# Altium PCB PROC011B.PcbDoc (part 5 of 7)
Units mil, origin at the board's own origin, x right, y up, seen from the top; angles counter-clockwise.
Board outline 3304 x 2569 mil, 6 copper layers (TOP, L2-GND1, L3-GND/SIG, L4-GND/SIG, L5-GND2, BOTTOM), stack 55.77 mil thick; 376 components, 289 nets, 1284 pads, 1755 vias.
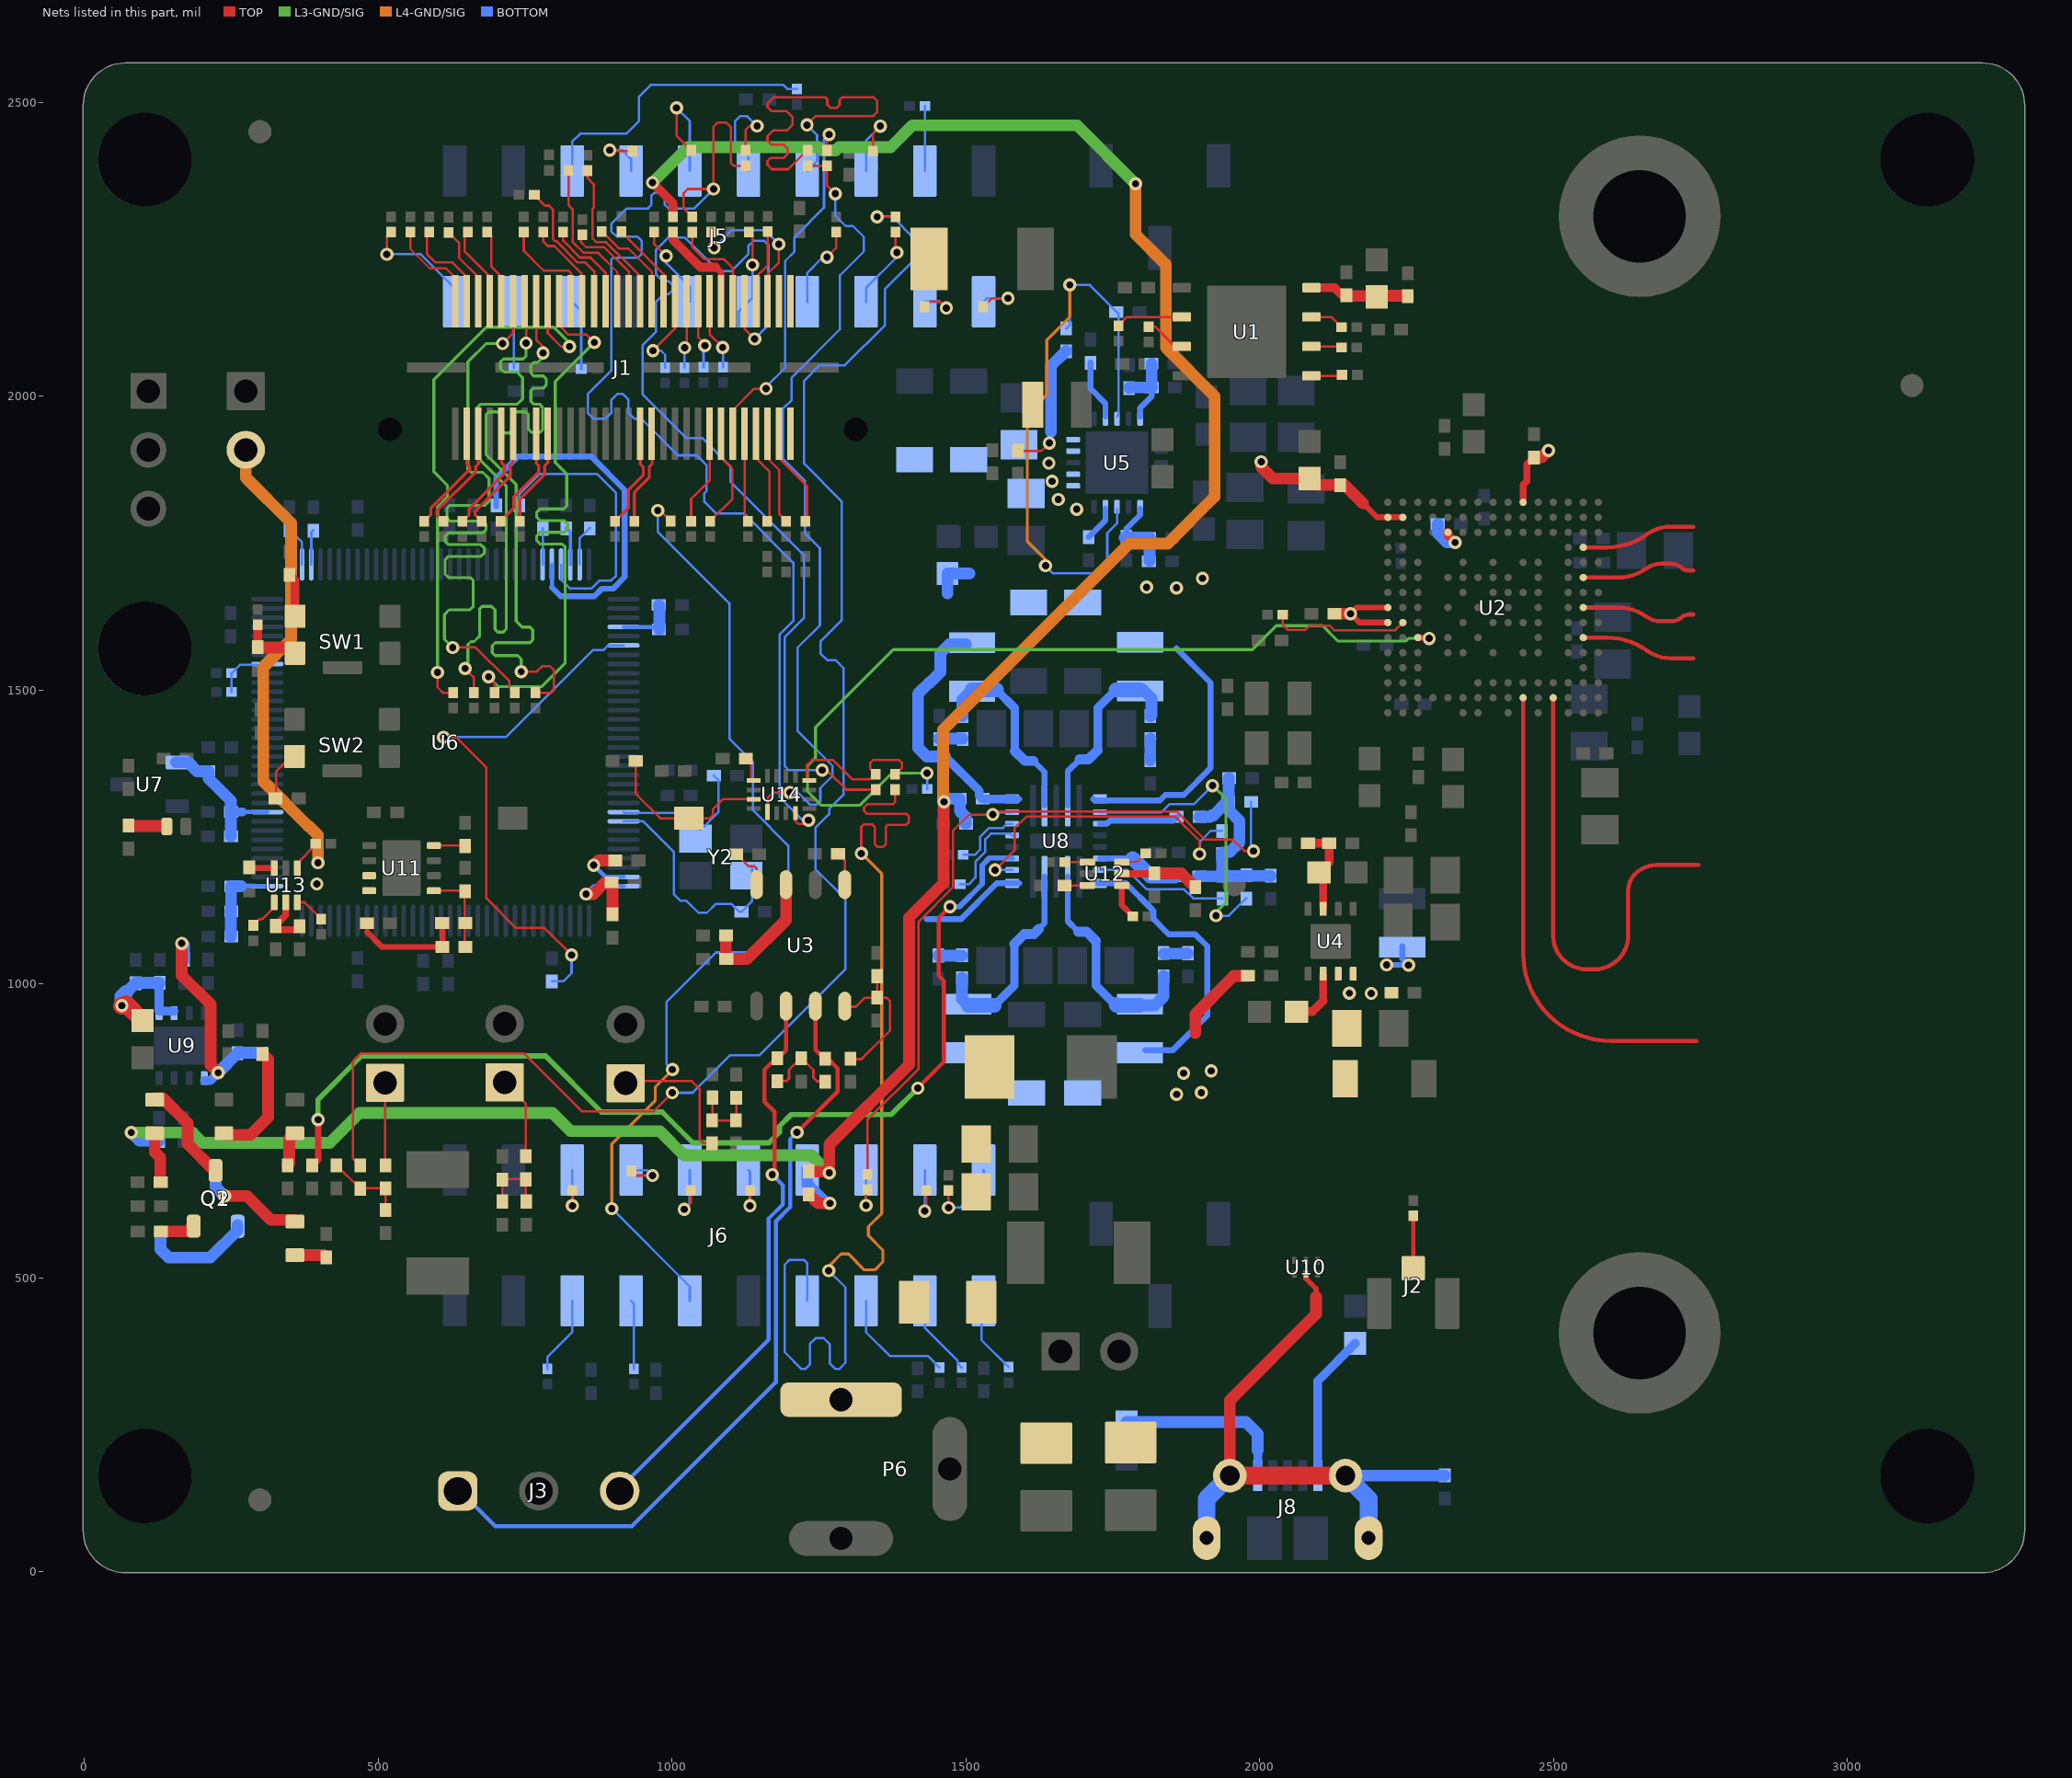
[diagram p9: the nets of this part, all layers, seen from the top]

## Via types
v1: diameter 22.4, hole 12.2, TOP to BOTTOM, tented both sides, 1046 vias
v2: diameter 13.77/15.74 (per signal layer), hole 5.9, TOP to L2-GND1, tented both sides, 699 vias
v3: diameter 19.68, hole 7.87, TOP to BOTTOM, tented both sides, 9 vias
v4: diameter 15.74, hole 5.9, TOP to L2-GND1, tented both sides, 1 vias

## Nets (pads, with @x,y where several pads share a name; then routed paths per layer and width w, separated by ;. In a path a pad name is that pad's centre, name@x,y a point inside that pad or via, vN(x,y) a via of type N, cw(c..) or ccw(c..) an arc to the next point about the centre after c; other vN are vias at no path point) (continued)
MCU_SOP2: R32.1 R101.2 | length 2731.1
  TOP w4: R101.2@469.73,690.25 469.34,690.64 456.75,703.23 456.75,868 470.75,882 748.05,882 846.65,783.4 969.15,783.4 v1(1000.55,814.8) ; v1(1348.96,2305.21) R32.1@1380.3,2305.21
  BOTTOM w4: v1(1000.55,814.8) 1035.05,814.8 1099.05,878.8 1149.05,878.8 1294.95,1024.7 1294.95,1144.76 1244.15,1195.56 1244.15,1265.26 1267.63,1288.74 1267.63,1297.52 1291.71,1321.6 1291.71,1333.55 1291.75,1333.59 1291.75,1537.5 1278.75,1550.5 1264.75,1550.5 1252.75,1562.5 1252.75,1582.6 1288.75,1618.6 1288.75,1821.1 1224.75,1885.1 1224.75,2026.11 1251.14,2052.5 1294.24,2052.5 1362.75,2121.01 1362.75,2182.5 1412.75,2232.5 1412.75,2267.5 1375.04,2305.21 v1(1348.96,2305.21)
MISO1: R6.2 R7.2 U14.1 | length 1407
  TOP w4: U14.1@1162.65,1292.68 1162.65,1316.11 1172.19,1325.65 v1(1200.62,1325.65) ; R6.2@1230.8,2392.23 R7.2@1264,2392.23 1264,2358.25 v1(1277.75,2344.5)
  BOTTOM w4: v1(1200.62,1325.65) 1214.1,1325.65 1234.35,1305.4 1246.43,1305.4 1252.45,1311.42 1252.45,1333.26 1273.22,1354.03 1273.22,1370.95 1213.58,1430.59 1213.58,1571.93 1251.65,1610 1251.65,1741.4 1226.45,1766.6 1226.45,1855.67 1188.97,1893.15 1188.97,1978.89 1203.75,1993.67 1203.75,2031.5 1285.75,2113.5 1285.75,2205.5 1326.45,2246.2 1326.45,2270.84 1307.79,2289.5 1295.75,2289.5 1277.75,2307.5 v1(1277.75,2344.5)
MOSI1: R4.2 R28.1 U14.4 | length 2092.4
  TOP w4: R28.1@1034.25,2304.89 1019.75,2319.39 1019.75,2345.5 1026.75,2352.5 v1(1070.75,2352.5) 1070.75,2458.72 1077.76,2465.73 1092.23,2465.73 1100.02,2457.94 1100.02,2396.91 1104.7,2392.23 R4.2@1125.3,2392.23 ; U14.4@1209.89,1290.71 1209.89,1276.91 1214.31,1272.49 1232.31,1272.49 1238.14,1272.49 1232.31,1278.32 v1(1232.31,1278.45)
  L3-GND/SIG w4: v1(1232.31,1278.45) 1234.92,1278.45 v1@1239,1274.37
  BOTTOM w4: v1(1070.75,2352.5) 1037.8,2319.55 994.1,2319.55 987.93,2325.72 987.93,2341.22 983.35,2345.8 969.59,2345.8 965.01,2341.22 965.01,2325.57 958.99,2319.55 923.08,2319.55 896.75,2293.22 896.75,2280.83 906.38,2271.2 941.7,2271.2 948.63,2264.27 948.63,2242.21 942.18,2235.76 900.12,2235.76 896.75,2232.39 896.75,2043.64 856.64,2003.53 856.64,1971.61 866.34,1961.91 887.35,1961.91 896.67,1971.23 896.67,1993.31 907.46,2004.1 916.27,2004.1 926.06,1994.31 926.06,1971.72 935.87,1961.91 947.65,1961.91 1010.13,1899.43 1042.02,1899.43 1059.12,1882.33 1059.12,1838.9 1055.05,1834.83 1055.05,1820.17 1074.63,1800.59 1122.39,1800.59 1206.65,1716.33 1206.65,1617.48 1183.11,1593.94 1183.11,1333.17 1182.92,1332.98 1182.92,1318.09 1226.64,1274.37 1230.72,1278.45 v1(1232.31,1278.45)
NetC1_2: C1.2 C2.2 R37.2 U1.8 | length 168.2
  TOP w15: U1.8@2090.08,2184.68 2127.56,2184.68 2140.14,2172.1 C2.2@2147.65,2172.1
  TOP w20: C2.2@2147.65,2172.1 2147.84,2171.91 2149.15,2170.6 2199.35,2170.6 2199.75,2171 R37.2@2252.25,2171
NetC16_2: C16.2 R78.1 U3.3 | length 230.9
  TOP w20: C16.2@1091.65,1082.5 1091.65,1042.5 R78.1@1092.43,1042.5 1127.75,1042.5 1194.06,1108.81 U3.3@1194.06,1168.83 U3.3@1194.06,1169.81
NetC18_1: C18.1 R81.2 R82.1 U4.3 | length 156
  TOP w13: C18.1@2101.12,1189.37 2108.13,1182.36 U4.3@2108.13,1130.54
  TOP w15: R81.2@2081.54,1239.67 R81.2@2082.33,1239.67 2118.38,1239.67 2118.38,1206.62 C18.1@2101.12,1189.37
NetC22_2: C22.2 U4.6 | length 96.1
  TOP w13: 2108.13,971.38 U4.6@2108.13,1014.4
  TOP w15: C22.2@2062.72,952.77 2062.95,953 2089.75,953 2108.13,971.38
NetC24_2: C24.2 R85.1 R87.2 | length 129.4
  TOP w4: R87.2@1179.45,835 1195.35,835 1199.25,838.9 1199.25,853.9 1218.25,872.9 1219.85,872.9 1221.45,872.9 1240.75,853.6 1240.75,840.5 1246.85,834.4 R85.1@1260.75,834.4
NetC26_1: C26.1 C27.1 D3.1 F1.1 FB1.1 FB2.1
NetC28_1: C28.1 R121.2 R122.1 U5.10 | length 138.7
  BOTTOM w10: U5.10@1796.74,1965.56 1796.74,1980.04 1816.35,1999.65 1816.35,2014.14 R122.1@1816.35,2014.92
  BOTTOM w12: R122.1@1816.35,2014.14 R122.1@1817.13,2014.92
  BOTTOM w20: R121.2@1778.02,2014.49 1778.45,2014.92 R122.1@1816.35,2014.92 1817.13,2014.92 1816.45,2015.6 C28.1@1816.45,2055.5
NetC29_2: C29.2 U5.7 | length 102.2
  BOTTOM w10: C29.2@1712.22,2057.25 C29.2@1712.22,2056.86 1712.22,2013.03 1737.68,1987.57 U5.7@1737.68,1965.56
NetC44_2: C44.2 U5.19 | length 59.9
  BOTTOM w10: C44.2@1708.92,1760.05 1709.11,1760.24 1737.68,1788.81 U5.19@1737.68,1808.08
NetC46_1: C46.1 R131.1 R132.2 U5.16 | length 147.1
  BOTTOM w10: R132.2@1770.69,1759.28 1773.22,1759.75 1771.22,1759.75 R132.2@1773.22,1761.75 ; R132.2@1773.22,1760.54 R132.2@1773.22,1761.75 ; U5.16@1796.74,1808.08 1796.74,1798.16 1773.22,1774.64 R132.2@1773.22,1761.75 ; C46.1@1811.95,1719.02 C46.1@1812.59,1719.66
  BOTTOM w20: R132.2@1770.69,1759.28 R131.1@1811.81,1759.28 1812.59,1759.28 C46.1@1812.59,1719.66
NetC49_2: C49.2 R134.1 U6.68 | length 104.2
  BOTTOM w7: U6.68@917.69,1607.39 974.21,1607.39 978.11,1603.49 R134.1@978.5,1603.1
  BOTTOM w20: C49.2@977.8,1644.4 978.5,1643.7 R134.1@978.5,1603.1
NetC63_2: C63.2 U6.88 Y2.1 | length 251.3
  BOTTOM w4: U6.88@917.69,1292.43 919.12,1291 1018.74,1291 1046.96,1262.78 1049.4,1262.78 1079.3,1292.68 1079.3,1346.36 C63.2@1071.31,1354.35
NetC66_2: C66.2 C67.2 R140.1 U6.9 U7.1 | length 250.2
  BOTTOM w7: 269.42,1292.43 U6.9@311.39,1292.43
  BOTTOM w15: C66.2@249.24,1292.6 C66.2@249.63,1292.6 269.25,1292.6 269.42,1292.43
  BOTTOM w20: U7.1@156.11,1376.99 U7.1@158.07,1376.99 176.75,1376.99 191.72,1362.02 R140.1@210.71,1362.02 211.5,1362.02 211.5,1349.25 249.24,1311.51 249.24,1292.6 249.24,1251.36 C67.2@249.3,1251.3
NetC70_2: C70.2 U6.89 Y2.3 | length 403.5
  BOTTOM w4: U6.89@917.69,1276.68 951.07,1276.68 1003.45,1224.3 1003.45,1152.38 1014.36,1141.47 1024.62,1141.47 1044.92,1121.18 1059.56,1121.18 1074.79,1136.41 1100.86,1136.41 1114.57,1122.7 C70.2@1118.25,1122.7 1136.02,1140.47 1136.02,1184.08 Y2.3@1136.02,1199.78
NetC71_2: C71.2 R154.1 U6.96 | length 174.6
  TOP w20: v1(853.75,1153) 866.39,1153 886.39,1173 C71.2@897.06,1173 C71.2@897.45,1173 ; R154.1@898.75,1118.18 C71.2@898.75,1171.31
  BOTTOM w7: v1(853.75,1153) 867.2,1166.45 U6.96@917.69,1166.45
NetC78_1: C78.1 R156.1 R157.2 U9.5 | length 394
  TOP w20: v1(165.75,1069) 165.75,1014.4 214.75,965.4 214.75,862 v1(227.75,849)
  BOTTOM w15: U9.5@203.97,835.82 214.57,835.82 v1(227.75,849)
  BOTTOM w20: v1(165.75,1069) 166.75,1069 169.85,1065.9 C78.1@169.85,1041.33 C78.1@169.85,1040.95 ; v1(227.75,849) R156.1@260.78,882 ; R156.1@260.78,882 260.78,882.79 301.61,882.79 R157.2@301.95,882.45
NetC79_2: C79.2 C80.2 R176.1 U9.1 U9.2 | length 211.7
  TOP w30: v1(63.75,963) 67.75,963 70.5,965.75 70.75,966 98.75,938 R176.1@98.75,937.5
  BOTTOM w15: C79.2@128.37,1002.05 128.18,1001.86 128.02,1001.7 127.19,1000.87 127.19,953.94 U9.2@152.78,953.94
  BOTTOM w20: 70.75,985.1 87.16,1001.51 87.35,1001.7 C79.2@128.02,1001.7
  BOTTOM w25: v1(63.75,963) 63.75,978.1 70.75,985.1
NetC85_2: C85.2 C88.1 P7.2 R61.2 U11.3 U11.4 | length 972.9
  TOP w10: 481.35,1088.1 506.55,1062.9 C88.1@609.07,1062.9 609.45,1062.9 609.65,1063.1 R61.2@609.65,1103.6
  L4-GND/SIG w20: P7.2@274.69,1908.65 274.69,1861.56 351.75,1784.5 351.75,1586.5 304.35,1539.1 304.35,1345.1 380.55,1268.9 381.85,1268.9 397.65,1253.1 v1(397.65,1206)
  other v1: 395.65,1170
NetC88_2: C88.2 R61.1 R193.2 U11.5 | length 145
  TOP w4: U11.5@598.71,1158.61 647.65,1158.61 647.45,1158.41 647.45,1157.82 647.45,1103.6 647.45,1063.5 C88.2@648.05,1062.9
NetC91_2: C91.2 R196.1 U12.5 | length 135.4
  TOP w12: U12.5@1765.38,1187.4 1820.65,1187.4 C91.2@1821.15,1187.9
  TOP w20: C91.2@1821.15,1187.9 1866.65,1187.9 1890.26,1164.29 R196.1@1890.65,1163.9
NetC92_2: C92.2 R200.1 U13.5 | length 94.9
  TOP w12: U13.5@342.75,1138.77 342.75,1117.3 324.3,1098.85 331.15,1092 360.35,1092 C92.2@366.35,1098
NetC93_2: C93.2 R202.1 | length 40.2
  BOTTOM w20: C93.2@1454.45,1417.1 1454.85,1417.5 R202.1@1494.45,1417.5
NetC94_2: C94.2 R203.1 | length 37.4
  BOTTOM w20: C94.2@1814.05,1380.1 C94.2@1814.05,1380.49 1814.05,1416.61 1814.05,1417.2 R203.1@1814.25,1417.4
NetC95_2: C95.2 R204.1 | length 40.4
  BOTTOM w20: C95.2@1453.15,1048 1453.34,1048.19 R204.1@1493.45,1048.2
NetC96_2: C96.2 R205.1 | length 41.3
  BOTTOM w20: R205.1@1836.65,1051.7 1877.65,1051.7 C96.2@1877.85,1051.9
NetD2_1: D2.1 R80.2 | length 67.8
  TOP w10: D2.1@139.05,1268.56 139.64,1267.97 D2.1@140.24,1267.97 D2.1@143.09,1267.97
  TOP w20: R80.2@75.5,1268.56 D2.1@139.05,1268.56
NetDS1_1: DS1.1 R90.1 | length 200
  TOP w20: DS1.1@237.46,743.13 282.88,743.13 312.75,773 312.75,871.85 303.6,881 R90.1@303.21,881.39
NetDS2_1: DS2.1 R100.1 | length 59.8
  TOP w20: R100.1@345.66,691.25 348.75,694.33 348.75,736.23 DS2.1@358.35,745.83
NetDS3_1: DS3.1 R103.1 | length 84.2
  TOP w20: DS3.1@119.78,742.81 119.78,713.97 129.22,704.53 R103.1@129.22,662.57
NetDS3_2: DS3.2 Q1.3 | length 175.9
  TOP w20: DS3.2@119.78,805.81 132.94,805.81 175.65,763.1 175.65,728.21 222.35,681.51 Q1.3@223.33,680.53
NetDS4_1: DS4.1 R117.1 | length 54.4
  TOP w20: DS4.1@358.35,538.42 407.91,538.42 R117.1@411.36,534.96
NetDS4_2: DS4.2 Q2.3 | length 183.7
  TOP w20: v1(238.75,639) 277.06,639 317.6,598.46 DS4.2@358.35,598.46
  BOTTOM w20: Q2.3@223.37,679.95 223.37,654.38 v1(238.75,639)
NetF1_2: F1.2 P6.1
NetJ1_1: J1.1 J1.2 J1.3 R34.1
NetJ1_4: J1.4 R67.1 | length 169.2
  TOP w4: J1.4@1182.55,1935.77 1182.55,1893.9 1229.75,1846.7 1229.75,1789.96 R67.1@1227,1787.21
NetJ1_5: J1.5 R29.2 | length 265.8
  TOP w4: R29.2@1066.58,2279.23 1066.58,2257.67 v1(1071.75,2252.5) ; J1.5@1162.86,2161.75 1162.86,2208.61 1181.75,2227.5 v1(1181.75,2258.5)
  BOTTOM w4: v1(1071.75,2252.5) 1101.75,2282.5 1157.75,2282.5 v1(1181.75,2258.5)
NetJ1_6: J1.6 R66.1 | length 161.7
  TOP w4: J1.6@1162.86,1935.77 1162.86,1893.9 1182.75,1874.01 1182.75,1798.96 R66.1@1194.5,1787.21
NetJ1_7: J1.7 R17.2 | length 126.7
  TOP w4: J1.7@1143.18,2161.75 1143.18,2202.93 1163,2222.75 R17.2@1163,2280.23
NetJ1_8: J1.8 R65.1 | length 159.6
  TOP w4: J1.8@1143.18,1935.77 1143.18,1894.58 1165.95,1871.81 1165.95,1791.16 R65.1@1162,1787.21
NetJ1_9: J1.9 R75.2 | length 1734.2
  TOP w4: J1.9@1123.49,2161.75 1123.49,2161.56 1123.49,2114.76 v1(1140.75,2097.5) ; v1(1255.52,1363.62) 1263.64,1363.62 1296.76,1330.51 R75.2@1346.75,1330.51
  BOTTOM w4: v1(1140.75,2097.5) 1164.05,2120.8 1164.05,2257.15 1156.46,2264.74 1139.39,2264.74 1129.85,2255.2 1129.85,2241.53 1100.94,2212.62 1079.22,2212.62 1022.14,2269.7 993.68,2269.7 972.45,2248.47 972.45,2207.63 984.38,2195.7 994.44,2195.7 1001.13,2189.01 1001.13,2180.38 994.43,2173.68 985.82,2173.68 972.45,2160.31 972.45,2109.37 949.76,2086.68 949.76,2003.46 1024.13,1929.09 1051.28,1929.09 1099.45,1880.92 1099.45,1854.8 1224.65,1729.6 1224.65,1622.75 1192.11,1590.21 1192.11,1370.14 1198.63,1363.62 v1(1255.52,1363.62)
NetJ1_10: J1.10 R64.1 | length 151
  TOP w4: J1.10@1123.49,1935.77 1123.49,1793.08 R64.1@1129.36,1787.21
NetJ1_11: J1.11 R28.2 | length 165.5
  TOP w4: R28.2@1034.25,2278.91 1034.25,2254 1054.75,2233.5 1088.16,2233.5 1103.81,2217.85 J1.11@1103.81,2161.75
NetJ1_12: J1.12 R7.1 | length 617.8
  TOP w4: J1.12@1103.4,1935.96 1103.4,1976.36 1139.88,2012.84 v1(1160.01,2012.84) ; J1.12@1103.81,1935.77 J1.12@1103.81,1935.96 ; R7.1@1264,2418.21 1264,2442.11 v1(1267.28,2445.39)
  BOTTOM w4: v1(1160.01,2012.84) 1160.01,2015.76 1192.62,2048.37 1192.62,2230.05 1208.45,2245.87 1208.45,2270.6 1258.75,2320.9 1258.75,2436.86 v1(1267.28,2445.39)
NetJ1_13: J1.13 R27.2 | length 167
  TOP w10: 1074.75,2219.5 1084.12,2210.13 J1.13@1084.12,2161.75
  TOP w15: R27.2@1001.55,2279.01 1001.55,2266.2 1048.25,2219.5 1074.75,2219.5
NetJ1_14: J1.14 R63.1 | length 172
  TOP w4: R63.1@1064.86,1787.21 1102.75,1825.1 1102.75,1875.89 1084.12,1894.52 J1.14@1084.12,1935.77
NetJ1_15: J1.15 R54.2 | length 121.7
  TOP w4: J1.15@1064.03,2161.56 1064.03,2105.22 v1(1086.25,2083) ; J1.15@1064.44,2161.56 J1.15@1064.44,2161.75
  BOTTOM w4: v1(1086.25,2083) 1086.75,2082.5 R54.2@1086.75,2049.49
NetJ1_16: J1.16 R62.1 | length 161.7
  TOP w4: R62.1@1032.6,1787.21 1032.6,1825.35 1064.44,1857.19 J1.16@1064.44,1935.77
NetJ1_17: J1.17 R55.2 | length 117.9
  TOP w4: J1.17@1044.75,2161.75 1044.75,2161.56 1044.75,2100.5 1055.87,2089.38 v1(1055.87,2086.09)
  BOTTOM w4: R55.2@1053.75,2049.29 1053.75,2075.5 1055.87,2077.62 v1(1055.87,2086.09)
NetJ1_19: J1.19 R56.2 | length 114.5
  TOP w4: v1(1021.75,2082.5) 1025.07,2085.82 1025.07,2161.56 J1.19@1025.07,2161.75
  BOTTOM w4: R56.2@1021.25,2048.79 1021.25,2082 v1(1021.75,2082.5)
NetJ1_21: J1.21 R57.2 | length 145
  TOP w4: v1(967.75,2077.5) 1005.38,2115.13 1005.38,2161.56 J1.21@1005.38,2161.75
  BOTTOM w4: v1(967.75,2077.5) 981.25,2077.5 988.35,2070.4 R57.2@988.35,2048.79
NetJ1_23: J1.23 R179.2 | length 148.1
  TOP w4: R179.2@913.75,2280.01 985.7,2208.06 J1.23@985.7,2161.75
NetJ1_25: J1.25 R180.2 | length 163.6
  TOP w4: R180.2@880.45,2280.21 881.04,2280.21 909.75,2251.5 925.75,2251.5 966.01,2211.24 J1.25@966.01,2161.75
NetJ1_26: J1.26 R59.1 | length 161.1
  TOP w5.2: R59.1@935.8,1787.21 935.8,1836.05 961.27,1861.52 961.27,1879.81 966.01,1884.55 J1.26@966.01,1935.77
NetJ1_27: J1.27 R181.2 | length 270.8
  TOP w4: R181.2@856.25,2383.81 856.25,2371 866.75,2360.5 866.75,2320.5 864.75,2318.5 864.75,2268.5 871.25,2262 887.85,2262 946.33,2203.52 J1.27@946.33,2161.75
NetJ1_28: J1.28 R58.1 | length 170.3
  TOP w5.2: R58.1@903.3,1787.21 925.6,1809.51 925.6,1840.28 951.07,1865.75 951.07,1879.81 946.33,1884.55 J1.28@946.33,1935.77
NetJ1_29: J1.29 R182.2 | length 166.1
  TOP w4: R182.2@847.75,2274.51 844.75,2271.51 844.75,2262.51 853.76,2253.5 884.75,2253.5 926.64,2211.61 J1.29@926.64,2161.75
NetJ1_31: J1.31 R183.2 | length 271.6
  TOP w4: R183.2@823.75,2384.21 823.75,2325.1 830.75,2318.1 830.75,2262.5 849.05,2244.2 874.05,2244.2 906.96,2211.29 J1.31@906.96,2161.75
NetJ1_33: J1.33 R184.2 | length 158.3
  TOP w4: R184.2@814.75,2279.51 814.75,2264.51 843.36,2235.9 861.35,2235.9 887.27,2209.98 J1.33@887.27,2161.75
NetJ1_35: J1.35 R185.2 | length 235.8
  TOP w4: R185.2@765.74,2342.5 783.94,2324.3 790.95,2324.3 797.35,2317.9 797.35,2267.9 801.75,2263.5 803.75,2263.5 839.65,2227.6 852.55,2227.6 867.59,2212.56 J1.35@867.59,2161.75
NetJ1_37: J1.37 R186.2 | length 151.9
  TOP w4: R186.2@781.05,2279.51 781.05,2263.2 788.75,2255.5 799.75,2255.5 845.75,2209.5 845.75,2163.9 847.79,2161.86 J1.37@847.9,2161.75
NetJ1_39: J1.39 R187.2 | length 176
  TOP w4: R187.2@747.75,2279.51 747.75,2247.5 781.75,2213.5 824.22,2213.5 828.22,2209.5 J1.39@828.22,2161.75
NetJ1_41: J1.41 R188.2 | length 1058.5
  TOP w4: v1(687.75,1522.6) 697.75,1512.6 R188.2@697.75,1495.59 ; J1.41@808.53,2161.75 808.53,2161.56 808.53,2119.92 823.95,2104.5 854.75,2104.5 v1(867.75,2091.5)
  L3-GND/SIG w5: v1(687.75,1522.6) 704.77,1505.58 777.83,1505.58 818.25,1546 818.25,1743.34 813.25,1748.34 775.61,1748.34 769.75,1754.2 769.75,1762.48 775.61,1768.34 816.89,1768.34 822.75,1774.2 822.75,1782.48 816.89,1788.34 775.61,1788.34 769.75,1794.2 769.75,1802.48 775.61,1808.34 815.85,1808.34 820.85,1813.34 820.85,1867.9 801.35,1887.4 801.35,2025.1 v1(867.75,2091.5)
NetJ1_43: J1.43 R189.2 | length 956.7
  TOP w4: v1(601.05,1530.2) 601.05,1504.6 610.06,1495.59 R189.2@627.75,1495.59 ; J1.43@788.44,2161.56 788.44,2107.29 811.23,2084.5 v1(825.75,2084.5) ; J1.43@788.85,2161.56 J1.43@788.85,2161.75
  L3-GND/SIG w5: v1(601.05,1530.2) 601.05,1811.8 617.75,1828.5 617.75,1848.5 594.75,1871.5 594.75,2028 684.25,2117.5 798.75,2117.5 825.75,2090.5 v1(825.75,2084.5)
NetJ1_44: J1.44 R53.1 | length 168.4
  TOP w5.2: R53.1@741,1787.21 741,1824.74 783.25,1866.99 783.25,1881.49 788.85,1887.09 J1.44@788.85,1935.77
NetJ1_45: J1.45 R190.2 | length 1191.9
  TOP w4: v1(743.45,1531.4) 769.65,1531.4 778.75,1540.5 792.75,1540.5 798.75,1534.5 798.75,1499.59 794.75,1495.59 R190.2@767.75,1495.59 ; J1.45@769.16,2161.75 769.16,2161.56 769.16,2096.09 780.75,2084.5 v1(780.75,2073.5) v1@780.75,2072.5
  L3-GND/SIG w5: v1(743.45,1531.4) 743.45,1552.7 737.55,1558.6 699.29,1558.6 694.29,1563.6 694.29,1575.5 699.29,1580.5 758.15,1580.5 763.15,1585.5 763.15,1602.2 758.15,1607.2 744.75,1607.2 734.75,1617.2 734.75,1849.5 683.75,1900.5 683.75,1968.5 688.75,1973.5 703.18,1973.5 709.04,1967.64 709.04,1943.36 714.9,1937.5 723.18,1937.5 729.04,1943.36 729.04,1967.64 734.9,1973.5 750.75,1973.5 755.75,1968.5 755.75,1943.5 760.75,1938.5 775.75,1938.5 779.75,1942.5 779.75,1981.5 774.75,1986.5 764.75,1986.5 759.75,1991.5 759.75,2009.5 763.75,2013.5 780.95,2013.5 785.95,2018.5 785.95,2029.5 780.95,2034.5 764.87,2034.5 759.87,2039.5 759.87,2052.5 764.87,2057.5 771.75,2057.5 780.75,2066.5 v1@780.75,2072.5
NetJ1_46: J1.46 R52.1 | length 176.9
  TOP w5.2: R52.1@708.5,1787.21 730.8,1809.51 730.8,1828.97 773.05,1871.22 773.05,1881.7 769.16,1885.59 J1.46@769.16,1935.77
NetJ1_47: J1.47 R191.2 | length 963.5
  TOP w4: v1(647.85,1536.7) 662.75,1521.8 R191.2@662.75,1495.59 ; J1.47@749.48,2161.75 751.75,2159.48 v1(751.75,2090.5)
  L3-GND/SIG w5: v1(647.85,1536.7) 652.75,1541.6 652.75,1577.5 657.75,1582.5 663.16,1582.5 672.75,1592.09 672.75,1638.5 676.75,1642.5 692.75,1642.5 698.75,1636.5 698.75,1603.5 703.75,1598.5 712.75,1598.5 717.85,1603.6 717.85,1847.4 667.75,1897.5 667.75,1979.51 674.74,1986.5 736.75,1986.5 745.75,1995.5 745.75,2031.5 736.25,2041 714.25,2041 708.29,2046.96 708.29,2058.5 713.29,2063.5 746.75,2063.5 751.75,2068.5 v1(751.75,2090.5)
NetJ1_49: J1.49 R192.2 | length 1204.6
  TOP w4: v1(626.75,1572.4) 665.85,1572.4 723.15,1515.1 723.15,1505.19 R192.2@732.75,1495.59 ; v1(711.75,2089.5) 729.79,2107.54 729.79,2161.56 J1.49@729.79,2161.75
  L3-GND/SIG w5: v1(626.75,1572.4) 612.75,1586.4 612.75,1628.5 620.75,1636.5 655.75,1636.5 661.75,1642.5 661.75,1686.5 656.75,1691.5 619.75,1691.5 613.75,1697.5 613.75,1721.57 619.61,1727.43 674.89,1727.43 680.75,1733.29 680.75,1741.57 674.89,1747.43 619.61,1747.43 613.75,1753.29 613.75,1761.57 619.61,1767.43 677.89,1767.43 683.75,1773.29 683.75,1781.57 677.89,1787.43 621.95,1787.43 616.95,1792.43 616.95,1809.3 621.95,1814.3 681.55,1814.3 688.75,1821.5 688.75,1859.8 678.05,1870.5 657.75,1870.5 652.75,1875.5 652.75,2058.35 683.9,2089.5 v1(711.75,2089.5)
NetJ1_50: J1.50 R51.1 | length 180.1
  TOP w5.2: R51.1@676,1787.21 664.85,1798.36 664.85,1804.11 724.75,1864.01 724.75,1883.01 729.79,1888.05 J1.50@729.79,1935.77
NetJ1_51: J1.51 R23.2 | length 127.7
  TOP w4: R23.2@685.36,2279.23 692.75,2271.84 692.75,2220.5 710.11,2203.14 J1.51@710.11,2161.75
NetJ1_52: J1.52 R50.1 | length 179.8
  TOP w5.2: R50.1@643.5,1787.21 654.65,1798.36 654.65,1808.34 714.55,1868.24 714.55,1882.21 710.11,1886.65 J1.52@710.11,1935.77
NetJ1_53: J1.53 R22.2 | length 137.5
  TOP w4: R22.2@652.86,2279.23 647.45,2273.82 647.45,2245.81 690.42,2202.84 J1.53@690.42,2161.75
NetJ1_55: J1.55 R33.2 | length 138
  TOP w4: R33.2@620.14,2278.79 637.75,2261.18 637.75,2235.5 670.74,2202.51 J1.55@670.74,2161.75
NetJ1_56: J1.56 R49.1 | length 182.6
  TOP w5.2: R49.1@611,1787.21 599.78,1798.43 599.78,1805.03 665.95,1871.2 665.95,1880.38 670.74,1885.17 J1.56@670.74,1935.77
NetJ1_57: J1.57 R21.2 | length 164.6
  TOP w4: R21.2@587.1,2279.23 582.75,2274.88 582.75,2242.51 597.76,2227.5 626.75,2227.5 651.05,2203.2 J1.57@651.05,2161.75
NetJ1_58: J1.58 R48.1 | length 182.6
  TOP w5.2: R48.1@578.36,1787.21 589.58,1798.43 589.58,1809.26 655.75,1875.43 655.75,1879.85 651.05,1884.55 J1.58@651.05,1935.77
NetJ1_59: J1.59 R20.2 | length 165.6
  TOP w4: R20.2@554.86,2279.23 554.86,2250.39 587.75,2217.5 615.76,2217.5 631.37,2201.89 J1.59@631.37,2161.75
NetJ2_1: J2.1 R111.2 | length 89.5
  TOP w7.08: J2.1@2261.46,516.26 2261.61,516.41 R111.2@2261.61,605.68
NetJ3_1: J3.1 R85.2 U3.7 | length 1370.5
  TOP w7: v1(1212.75,747.5) 1281.85,816.6 1281.85,856.3 1265.95,872.2 1260.75,872.2 1259.75,872.2 1244.06,887.89 U3.7@1244.06,961.15
  BOTTOM w7: J3.1@635.55,141.16 637.52,139.19 699.18,77.53 931.78,77.53 1176.75,322.5 1176.75,596.1 1200.95,620.3 1200.95,735.7 v1(1212.75,747.5)
NetJ3_3: J3.3 R87.1 U3.6 | length 968.7
  TOP w7: v1(1170.75,675.5) 1174.75,679.5 1174.75,782.3 1157.25,799.8 1157.25,854 1176.05,872.8 1179.45,872.8 1179.84,873.19 1194.06,887.41 U3.6@1194.06,961.15
  BOTTOM w7: J3.3@911.14,141.16 1164.75,394.77 1164.75,601.1 1188.95,625.3 1188.95,657.3 v1(1170.75,675.5)
NetJ5_1: J5.1 R19.2 | length 203
  TOP w4: v1(514.75,2241.5) 514.75,2271.98 R19.2@522,2279.23
  BOTTOM w4: v1(514.75,2241.5) 572.25,2241.5 630.25,2183.5 J5.1@630.25,2160.78
NetJ5_3: J5.3 R24.2 | length 112.9
  BOTTOM w4: J5.3@730.25,2160.78 730.86,2160.17 R24.2@730.86,2048.1
NetJ5_5: J5.5 R25.2 | length 120.8
  BOTTOM w4: J5.5@830.25,2160.78 845.56,2145.47 R25.2@845.56,2046.3
NetJ5_6: J5.6 R1.1 | length 499.1
  BOTTOM w4: J5.6@830.25,2383.22 830.25,2432.9 843.85,2446.5 922.35,2446.5 943.45,2467.6 943.45,2509.1 963.75,2529.4 1189.81,2529.4 1196.72,2522.49 R1.1@1212.55,2522.49
NetJ5_8: J5.8 R9.1 | length 102
  TOP w4: v1(893.95,2418.7) 895.44,2417.21 R9.1@932.5,2417.21
  BOTTOM w4: v1(893.95,2418.7) 914.95,2418.7 930.25,2403.4 J5.8@930.25,2383.22
NetJ5_9: J5.9 R26.2 | length 143.5
  TOP w4: R26.2@969.45,2279.11 969.45,2259.2 v1(990.15,2238.5)
  BOTTOM w4: v1(990.15,2238.5) 990.15,2226.45 1030.25,2186.35 J5.9@1030.25,2160.78
NetJ5_10: J5.10 R2.1 | length 199.3
  TOP w4: v1(1007.75,2490.5) 1007.75,2443.26 R2.1@1032.8,2418.21
  BOTTOM w4: v1(1007.75,2490.5) 1030.25,2468 J5.10@1030.25,2383.22
NetJ5_11: J5.11 R18.2 | length 172.7
  TOP w4: R18.2@1130.96,2279.58 1131.17,2279.58 1136.85,2273.9 v1(1136.85,2223.5)
  BOTTOM w4: J5.11@1113.17,2119.29 1113.17,2143.7 J5.11@1130.25,2160.78 1136.85,2167.38 v1(1136.85,2223.5)
NetJ5_12: J5.12 R4.1 | length 199.5
  TOP w4: R4.1@1125.3,2418.21 1125.3,2453.37 1131.58,2459.65 v1(1144.9,2459.65)
  BOTTOM w4: J5.12@1130.25,2383.22 1130.25,2410.9 1107.4,2433.75 1107.4,2468.08 1115.64,2476.32 1128.23,2476.32 v1(1144.9,2459.65)
NetJ5_13: J5.13 R31.2 | length 142.9
  TOP w4: v1(1263.75,2236.5) 1279.5,2252.25 R31.2@1279.5,2279.23
  BOTTOM w4: J5.13@1230.25,2160.78 1230.25,2209.97 1256.78,2236.5 v1(1263.75,2236.5)
NetJ5_14: J5.14 R6.1 | length 765.3
  TOP w4: v1(1229.75,2461.5) 1244.95,2476.7 1342.73,2476.7 1349.14,2483.11 1349.14,2502.84 1343.4,2508.58 1289.89,2508.58 1285.34,2504.03 1285.34,2495.57 1280.64,2490.87 1269.58,2490.87 1264.22,2496.23 1264.22,2505.35 1260.99,2508.58 1173.01,2508.58 1162.45,2498.02 1162.45,2491.95 1169.58,2484.82 1195.05,2484.82 1205.35,2474.52 1205.35,2462.24 1195.06,2451.95 1172.03,2451.95 1162.45,2442.37 1162.45,2434.73 1169.38,2427.8 1190.59,2427.8 1196.18,2422.21 1196.18,2411.25 1190.37,2405.44 1168.04,2405.44 1162.45,2399.85 1162.45,2393.77 1170.05,2386.17 1197.52,2386.17 1229.56,2418.21 R6.1@1230.8,2418.21
  BOTTOM w4: v1(1229.75,2461.5) 1247.02,2444.23 1247.02,2399.99 J5.14@1230.25,2383.22
NetJ5_15: J5.15 R32.2 | length 141.2
  TOP w4: R32.2@1380.3,2279.23 1380.75,2278.78 1380.75,2246.5 v1(1382.75,2244.5)
  BOTTOM w4: J5.15@1330.25,2160.78 1330.25,2184 1382.75,2236.5 v1(1382.75,2244.5)
NetJ5_16: J5.16 R10.1 | length 134
  TOP w4: R10.1@1342,2417.21 1342,2446.75 v1(1354.75,2459.5)
  BOTTOM w4: J5.16@1330.25,2383.22 1330.25,2435 v1(1354.75,2459.5)
NetJ5_17: J5.17 R35.2 | length 86.4
  TOP w4: R35.2@1429.5,2152.21 1438.29,2161 1455.75,2161 v1(1466.75,2150)
  BOTTOM w4: J5.17@1430.25,2160.78 1455.97,2160.78 v1(1466.75,2150)
NetJ5_18: J5.18 R8.1 | length 110.3
  BOTTOM w4: J5.18@1430.25,2383.22 R8.1@1430.25,2493.5
NetJ5_19: J5.19 R36.2 | length 91.5
  TOP w4: R36.2@1530,2152.21 1544.29,2166.5 v1(1571.75,2166.5)
  BOTTOM w4: J5.19@1530.25,2160.78 1535.97,2166.5 v1(1571.75,2166.5)
NetJ6_5: J6.5 R169.2 | length 133.6
  BOTTOM w4: R169.2@787.88,344.77 787.88,364.83 830.25,407.2 J6.5@830.25,460.78
NetJ6_6: J6.6 R104.1 | length 87.1
  TOP w4: v1(830.5,622.5) R104.1@830.5,648.79
  BOTTOM w4: J6.6@830.25,683.22 830.25,622.75 v1(830.5,622.5)
NetJ6_7: J6.7 R166.2 | length 118.2
  BOTTOM w4: J6.7@930.25,460.78 935.5,455.53 R166.2@935.5,344.77
NetJ6_8: J6.8 R94.1 | length 79.3
  TOP w4: R94.1@931,681.79 938.79,674 v1(966.75,674)
  BOTTOM w4: J6.8@930.25,683.22 957.53,683.22 v1(966.75,674)
NetJ6_9: J6.9 R165.2 | length 1685.5
  TOP w4: v1(975.75,1805.5) 979.74,1805.5 R165.2@997.75,1787.49
  L4-GND/SIG w5: v1(897.75,617.5) 897.75,727.85 971.75,801.85 971.75,825.08 1000.65,853.98 v1(1000.65,854.2)
  BOTTOM w4: v1(897.75,617.5) 1030.25,485 J6.9@1030.25,460.78 ; v1(975.75,1805.5) 975.75,1769.5 1097.75,1647.5 1097.75,1417.25 1137.92,1377.08 1137.92,1295.52 1198.05,1235.39 1198.05,1122.8 1128.75,1053.5 1074.75,1053.5 990.55,969.3 990.55,864.3 v1(1000.65,854.2)
NetJ6_10: J6.10 R105.1 | length 108
  TOP w4: v1(1020.75,616.4) 1032.5,628.15 R105.1@1032.5,648.79
  BOTTOM w4: v1(1020.75,616.4) 1030.25,625.9 J6.10@1030.25,683.22
NetJ6_12: J6.12 R106.1 | length 88.1
  TOP w4: v1(1132.75,622.5) 1133,622.75 R106.1@1133,648.79
  BOTTOM w4: J6.12@1130.25,683.22 1132.75,680.72 v1(1132.75,622.5)
NetJ6_13: J6.13 R76.2 | length 1850.2
  TOP w4: v1(1322.35,1221.9) 1322.15,1222.1 1322.15,1267.4 1326.15,1271.4 1340.95,1271.4 1344.95,1267.4 1344.95,1238.4 1350.35,1233 1358.85,1233 1364.25,1238.4 1364.25,1267.5 1367.75,1271 1399.05,1271 1403.05,1275 1403.05,1285.62 1399.04,1289.63 1331.84,1289.63 1326.85,1294.62 1326.85,1300.18 1332.3,1305.63 1375.06,1305.63 1379.75,1310.32 R76.2@1379.75,1330.51
  L4-GND/SIG w5: v1(1266.75,512) 1266.75,519.5 1287.73,540.48 1300.29,540.48 1327.37,513.4 1345.04,513.4 1358.85,527.21 1358.85,547.11 1334.33,571.62 1334.33,587.08 1356.85,609.6 1356.85,1187.4 v1(1322.35,1221.9)
  BOTTOM w4: J6.13@1230.25,460.78 1230.25,524.45 1224.09,530.61 1200.24,530.61 1191.85,522.22 1191.85,373.64 1220.69,344.8 1226.9,344.8 1234.66,352.56 1234.66,387.23 1244.68,397.25 1258.36,397.25 1268.56,387.05 1268.56,354.24 1278,344.8 1284.62,344.8 1295.11,355.29 1295.11,483.64 v1(1266.75,512)
NetJ6_14: J6.14 R107.1 | length 119.2
  TOP w20: R107.1@1232.5,642.88 1232.89,642.49 1248.88,626.5 v1(1268.75,626.5)
  BOTTOM w20: J6.14@1230.25,683.22 1230.25,659 1262.75,626.5 v1(1268.75,626.5)
NetJ6_15: J6.15 R164.2 | length 203.5
  BOTTOM w4: J6.15@1330.25,460.78 1330.25,407.5 1371.25,366.5 1436.21,366.5 R164.2@1455.5,347.21
NetJ6_16: J6.16 R102.1 | length 88.1
  TOP w4: v1(1330.25,623) 1330.25,647.04 R102.1@1333,649.79
  BOTTOM w4: v1(1330.25,623) J6.16@1330.25,683.22
NetJ6_17: J6.17 R163.2 | length 139.6
  BOTTOM w4: J6.17@1430.25,460.78 1430.25,414.73 1485.75,359.23 1485.75,354.46 R163.2@1493,347.21
NetJ6_18: J6.18 R108.1 | length 106
  TOP w4: v1(1430.25,613.5) 1433.1,616.35 R108.1@1433.1,648.59
  BOTTOM w4: v1(1430.25,613.5) J6.18@1430.25,683.22
NetJ6_19: J6.19 R162.2 | length 133.6
  BOTTOM w4: J6.19@1530.25,460.78 1526.75,457.28 1526.75,394.02 R162.2@1573,347.77
NetJ6_20: J6.20 R109.1 | length 129.5
  TOP w4: v1(1470.6,619.3) R109.1@1470.6,648.59
  BOTTOM w4: v1(1470.6,619.3) 1490.36,619.3 1530.25,659.19 J6.20@1530.25,683.22
NetJ8_1: J8.1 R161.1 | length 251.7
  BOTTOM w10: J8.1@2098.75,163.56 J8.1@2098.93,163.38
  BOTTOM w15: J8.1@2098.75,163.56 2098.75,324.5 R161.1@2162.75,388.5
NetJ8_5: J8.5 R175.2 | length 302.5
  BOTTOM w15: J8.5@1996.57,163.38 1996.75,163.56 1996.75,206.5
  BOTTOM w20: R175.2@1773.75,254.5 1976.75,254.5 1996.75,234.5 1996.75,206.5
NetJ8_6: J8.6 J8.9 J8.10 J8.11 R174.2 U10.5 | length 1021.8
  TOP w9: U10.5@2078.75,506.19 2078.75,498.49 2095.96,481.28
  TOP w10: 2095.96,467.21 2095.96,481.28
  TOP w20: J8.10@1949.32,163.38 1949.32,291.57 2095.96,438.21 2095.96,467.21
  TOP w30: J8.10@1949.32,163.38 J8.11@2146.18,163.38
  BOTTOM w20: J8.11@2146.18,163.38 2315.06,163.38 R174.2@2315.15,163.29
  BOTTOM w30: J8.9@1909.95,57.08 1909.95,124.01 J8.10@1949.32,163.38 ; J8.11@2146.18,163.38 2185.55,124.01 J8.6@2185.55,57.08
NetP2_1: P2.1 R95.2 | length 141.4
  TOP w4: P2.1@715.19,832.25 751.57,795.87 R95.2@751.57,706.74 R95.2@751.57,705.95
NetP3_1: P3.1 R99.2 | length 141.6
  TOP w4: P3.1@511.75,831.92 511.75,691.34 511.75,691.17 511.98,690.94 R99.2@512.37,690.55
NetP4_1: P4.1 R92.2 | length 242.7
  TOP w4: P4.1@921.19,831.25 924.64,834.7 1033.75,834.7 1046.75,821.7 1046.75,735.51 1052.81,729.45 R92.2@1068.37,729.45
NetQ1_1: Q1.1 R116.2 | length 61.1
  TOP w20: R116.2@129.43,578.83 R116.2@130.22,578.83 174.79,578.83 184.95,588.99 Q1.1@185.93,589.97
NetQ2_1: Q2.1 R160.2 | length 195
  BOTTOM w20: R160.2@129.35,578.41 129.35,548.4 143.5,534.25 214,534.25 260.77,581.02 Q2.1@260.77,587.43 Q2.1@260.77,589.39
NetR3_1: R3.1 U12.3 | length 40.2
  TOP w4: R3.1@1666.95,1167.6 1667.06,1167.71 1667.74,1167.71 U12.3@1707.12,1167.71
NetR5_2: R5.2 U12.1 | length 38.5
  TOP w4: R5.2@1668.64,1207 1668.73,1207.09 U12.1@1707.12,1207.09
NetR11_2: R11.2 U3.1 | length 57.3
  TOP w4: R11.2@1282.64,1221.42 1294.06,1210 U3.1@1294.06,1168.83
NetR12_2: R12.2 U3.4 | length 72.4
  TOP w4: R12.2@1109.22,1220.7 1109.67,1220.7 1130.38,1199.99 1140.28,1199.99 1144.06,1196.21 U3.4@1144.06,1168.83
NetR39_2: R39.2 U1.2 | length 112.1
  TOP w4: R39.2@1759.65,2119.99 1774.34,2134.68 U1.2@1865.68,2134.68
NetR40_1: R40.1 U1.7 | length 56.5
  TOP w4: U1.7@2090.08,2134.68 2122.11,2134.68 R40.1@2139.44,2117.35
NetR42_2: R42.2 U1.3 | length 68.4
  TOP w4: R42.2@1811.25,2118.29 1822.27,2118.29 1855.88,2084.68 U1.3@1865.68,2084.68
NetR44_1: R44.1 U1.6 | length 50.1
  TOP w4: U1.6@2090.08,2084.68 2137.61,2084.68 R44.1@2139.44,2082.85
NetR45_1: R45.1 U1.5 | length 51.1
  TOP w4: U1.5@2090.08,2034.68 2138.77,2034.68 R45.1@2140.44,2036.35
NetR68_1: R68.1 SW1.4 | length 69.3
  TOP w15: R68.1@348.79,1696.75 349.18,1696.36 358.69,1686.85 SW1.4@358.69,1631.52
NetR72_1: R72.1 R73.2 SW1.2 | length 104.1
  TOP w15: R73.2@294.8,1572.32 295.19,1572.71 295.25,1572.77 295.25,1573.11 R72.1@295.25,1610.76
  TOP w20: R73.2@294.8,1572.32 354.89,1572.32 SW1.2@358.69,1568.52
NetR79_2: R79.2 SW2.2 | length 90.4
  TOP w4: R79.2@326.1,1315.64 326.1,1361.26 354.79,1389.95 SW2.2@357.74,1392.9
NetR86_1: R86.1 R177.2 R178.1 U3.8 | length 261.2
  TOP w4: U3.8@1294.06,961.15 1312.86,961.15 1327.81,976.1 R86.1@1349.05,976.1 ; R178.1@1303.55,872 1322.45,872 1371.05,920.6 1371.05,970.9 1365.85,976.1 R86.1@1349.05,976.1 ; R177.2@1349.25,1013.95 R177.2@1349.25,1013.16 1349.25,994.5 1349.05,994.3 R86.1@1349.05,976.89 R86.1@1349.05,976.1
NetR88_2: R88.2 R89.2 R92.1 R93.1 | length 120.8
  TOP w4: R88.2@1068.87,807.45 R88.2@1068.87,806.66 1068.87,768.04 1068.87,767.75 1068.76,767.64 1068.37,767.25 1108.57,767.25 1108.96,767.64 R93.1@1109.33,768.01 ; R93.1@1109.33,768.04 R89.2@1109.33,806.36 R89.2@1109.33,807.15
NetR95_1: R95.1 R96.2 R112.1 R113.2 | length 118.5
  TOP w4: R113.2@711.67,628.95 711.53,629.09 711.53,629.74 R96.2@711.53,667.06 711.53,667.85 751.27,667.85 751.57,668.15 R95.1@751.57,667.36 751.57,629.74 751.57,629.45 751.68,629.34 R112.1@752.07,628.95
NetR98_2: R98.2 R99.1 R101.1 R114.2 | length 137.9
  TOP w4: R98.2@428.57,690.55 430.19,690.55 468.29,652.45 469.73,652.45 470.03,652.75 512.37,652.75 R99.1@512.37,651.96 512.37,615.34 512.37,614.65 R114.2@512.27,614.55
NetR123_1: R123.1 U6.63 | length 69.2
  BOTTOM w4: U6.63@842.89,1713.69 842.89,1758.61 859.64,1775.36 R123.1@860.03,1775.75
NetR124_1: R124.1 U6.61 | length 487.2
  BOTTOM w4: R124.1@740.47,1813.25 R124.1@740.47,1814.04 740.47,1833.72 774.25,1867.5 872.75,1867.5 904.75,1835.5 904.75,1694.5 896.75,1686.5 876.75,1686.5 863.25,1673 826.25,1673 811.75,1687.5 811.75,1713.33 U6.61@811.39,1713.69
NetR125_2: R125.2 U6.59 | length 61.9
  BOTTOM w4: U6.59@779.89,1713.69 779.89,1774.66 779.89,1775.07 R125.2@780.27,1775.45
NetR126_1: R126.1 U6.62 | length 64.8
  BOTTOM w6: R126.1@820.43,1775.75 820.82,1775.36 827.14,1769.04 U6.62@827.14,1713.69
NetR127_1: R127.1 U6.60 | length 636.2
  BOTTOM w7: 795.64,1674.61 U6.60@795.64,1713.69
  BOTTOM w10: R127.1@700.87,1813.25 R127.1@700.87,1814.04 700.87,1860.61 737.76,1897.5 862.75,1897.5 919.75,1840.5 919.75,1692.5 899.75,1672.5 880.75,1672.5 867.75,1659.5 810.75,1659.5 795.64,1674.61
NetR128_2: R128.2 U6.33 | length 67.5
  BOTTOM w4: R128.2@349.25,1772.45 349.64,1772.06 370.45,1751.25 U6.33@370.45,1713.69
NetR129_2: R129.2 U6.34 | length 59.9
  BOTTOM w4: U6.34@386.19,1713.69 386.19,1768.54 389.36,1771.71 R129.2@389.75,1772.1
NetR135_2: R135.2 R136.2 U6.25 | length 99.3
  BOTTOM w4: R136.2@250.52,1496.79 R135.2@250.52,1528.69 264.83,1543 309.99,1543 U6.25@311.39,1544.4
NetR143_1: R143.1 U8.16 | length 135.7
  BOTTOM w10: U8.16@1728.55,1272.53 1740.28,1272.53 1745.75,1278 1853.05,1278 1858.96,1283.91 R143.1@1859.35,1284.3
NetR144_1: R144.1 U8.6 | length 117.6
  BOTTOM w4: R144.1@1496.04,1219.6 1515.35,1219.6 1524.15,1228.4 1524.15,1250.2 1539.45,1265.5 1563.25,1265.5 1570.28,1272.53 U8.6@1578.95,1272.53
NetR146_2: R146.2 U8.5 | length 153.9
  BOTTOM w4: R146.2@1490.34,1169.5 1504.94,1169.5 1516.25,1180.81 1516.25,1208 1518.85,1210.6 1519.15,1210.6 1533.15,1224.6 1533.15,1246.1 1542.55,1255.5 1576.29,1255.5 U8.5@1578.95,1252.84
NetR147_1: R147.1 U8.19 | length 142.9
  BOTTOM w10: U8.19@1728.55,1213.47 1783.98,1213.47
  BOTTOM w20: R147.1@1854.75,1183 R147.1@1858.07,1183 R147.1@1858.85,1183
  BOTTOM w25: 1783.98,1213.47 1814.45,1183 R147.1@1854.75,1183
NetR152_1: R152.1 U6.95 | length 99.3
  TOP w20: v1(866.75,1202) 874.75,1210 R152.1@903.61,1210
  BOTTOM w7: v1(866.75,1202) 886.56,1182.19 U6.95@917.69,1182.19
NetR155_1: R155.1 U6.70 | length 943.3
  TOP w4: v1(611.15,1419.8) 632.49,1419.8 684.01,1368.28 684.01,1145.62 734.46,1095.17 783.29,1095.17 v1(829.15,1049.3)
  BOTTOM w4: v1(611.15,1419.8) 717.25,1419.8 865.25,1567.8 883.24,1567.8 891.33,1575.89 U6.70@917.69,1575.89 ; R155.1@795.53,1004.75 815.49,1004.75 829.15,1018.41 v1(829.15,1049.3)
NetR167_2: R167.2 U12.4 | length 60.5
  TOP w10: U12.4@1765.38,1167.71 1765.38,1134.08 R167.2@1784.36,1115.1
NetR168_1: R168.1 U12.6 | length 47.3
  TOP w4: U12.6@1765.38,1207.09 1791.05,1207.09 R168.1@1806.36,1222.4
NetR194_2: R194.2 U11.8 | length 48.9
  TOP w4: U11.8@598.71,1235.39 R194.2@647.65,1235.39
NetR197_1: R197.1 U13.3 | length 42.8
  TOP w10: R197.1@280.55,1197.8 281.32,1197.03 U13.3@323.07,1197.03
NetR198_2: R198.2 U13.1 | length 54.1
  TOP w4: U13.1@362.44,1197.03 362.44,1205.58 393.36,1236.5 R198.2@393.36,1238.3
NetR199_1: R199.1 U13.6 | length 52.4
  TOP w4: U13.6@362.44,1138.77 374.57,1138.77 R199.1@403.05,1110.29
NetR201_1: R201.1 U13.4 | length 56.6
  TOP w4: R201.1@287.65,1099.69 297.96,1110 302.84,1110 323.06,1130.22 U13.4@323.07,1138.77
NetR206_1: R206.1 S2.2 U14.15 | length 295.6
  TOP w4: R206.1@938.29,1379.34 938.29,1323.5 979.94,1281.85 S2.2@1028.93,1281.85 1064.17,1281.85 1070,1287.68 1070,1297.5 1087.16,1314.66 1137.1,1314.66 1139.03,1312.73 U14.15@1139.03,1314.34
NetR208_1: R208.1 U14.13 | length 43.5
  TOP w4: R208.1@1125.5,1383.62 1134.79,1374.34 1134.79,1345.83 U14.13@1134.79,1344.01
NetR210_2: R210.2 U2.G14 | length 236.9
  TOP w4: R210.2@2039.47,1628.29 2039.47,1610.55 2047.52,1602.5 2077.75,1602.5 2084.75,1609.5 2119.51,1609.5 2127.31,1601.7 2212.85,1601.7 2212.95,1601.8 2230.75,1601.8 U2.G14@2243.76,1614.81
NetR211_2: R211.2 U2.F13 | length 1524.1
  TOP w10: U2.F13@2269.35,1589.22 v1@2287.1,1589.22
  L3-GND/SIG w5: v1(1434.15,1358.68) 1374.01,1358.68 1319.09,1303.76 1254.42,1303.76 1230.71,1327.46 1230.71,1371.26 1244.21,1384.76 1244.21,1436.26 1376.75,1568.8 1987.75,1568.8 2028.55,1609.6 2107.15,1609.6 2133.65,1583.1 2248.46,1583.1 2253.18,1587.82 v1(2288.5,1587.82)
  BOTTOM w4: R211.2@1434.15,1331.73 v1(1434.15,1358.68)
PGOOD: R27.1 R107.2 R138.2 R141.2 R159.1 | length 4455.5
  TOP w15: v1(966.75,2363.5) 1001.55,2328.7 R27.1@1001.55,2304.99
  TOP w20: R107.2@1232.5,680.68 1262.61,680.68 1264.79,678.5 v1(1267.75,678.5) 1267.75,726.9 1403.55,862.7 1403.55,1112.9 1462.25,1171.6 1462.25,1309.1 v1(1462.85,1309.7)
  L3-GND/SIG w20: v1(79.75,747) 184.25,747 201.55,729.7 417.55,729.7 468.35,780.5 796.56,780.5 827.56,749.5 979.29,749.5 1020.29,708.5 1237.75,708.5 v1(1267.75,678.5) ; v1(966.75,2363.5) 1027.16,2423.91 1250.29,2423.91 1256.01,2418.19 1278.55,2418.19 1284.27,2423.91 1372.16,2423.91 1409.3,2461.05 1689.2,2461.05 v1(1788.75,2361.5)
  L4-GND/SIG w20: v1(1462.85,1309.7) 1461.35,1311.2 1461.35,1432.5 1778.05,1749.2 1843.65,1749.2 1923.35,1828.9 1923.35,2000.11 1840.65,2082.81 1840.65,2223.9 1788.75,2275.8 v1(1788.75,2361.5)
  BOTTOM w20: v1(79.75,747) 93.44,733.31 R159.1@127.18,733.31 ; v1(1462.85,1309.7) 1468.55,1315.4 R141.2@1489.16,1315.4 1489.95,1315.4 1489.95,1294 1499.75,1284.2 R138.2@1499.75,1272.4
PMIC_1V2: C3.2 C4.2 C6.2 C7.2 C54.2 C89.2 L1.2 U2.G15 U2.H15 U2.N11 U2.P14 U2.P15 U2.R6 U8.14 | length 1089.9
  TOP w10: 2176.25,1817.5 2199.81,1793.94 U2.P15@2218.17,1793.94 U2.P14@2243.76,1793.94 ; U2.G15@2218.17,1614.81 2169.79,1614.81 v1(2154.75,1629.85) 2165.3,1640.4 U2.H15@2218.17,1640.4
  TOP w12: U2.R6@2448.48,1819.53 2448.48,1848.23 2448.75,1848.5 2448.75,1849.5 2454.75,1855.5 2454.75,1883.95 2466.76,1895.96 C3.2@2466.95,1896.15
  TOP w15: U2.N11@2320.53,1768.35 2320.53,1763.27 v1(2332.7,1751.1)
  TOP w20: v1(2002.75,1888.5) 2002.75,1879.6 2022.45,1859.9 C89.2@2084.85,1859.9 2095.95,1848.8 2137.25,1848.8 2144.95,1848.8 2176.25,1817.5 ; C4.2@2127.02,1629.85 C4.2@2127.41,1629.85 v1(2154.75,1629.85) ; C3.2@2466.95,1896.15 2480.1,1896.15 v1(2491.45,1907.5)
  BOTTOM w10: 1716.55,1314.65 1719.3,1311.9 1728.55,1311.9 1830.45,1311.9 1839.95,1321.4 1870.85,1321.4 1916.65,1367.2 1916.65,1512.6 1858.25,1571
  BOTTOM w20: C7.2@2303.45,1782.5 2303.45,1766.8 2319.15,1751.1 v1(2332.7,1751.1)
  other v1: 1858.45,1673.9 1807.75,1675 1902.75,1690
PMIC_1V8: C30.2 C31.2 C32.2 C40.2 C81.2 L4.2 L6.1 R46.1 R120.2 U5.1 U5.2 U5.4 U5.5 U8.1 | length 390.9
  TOP w4: R46.1@1588.35,1906.7 1628.45,1906.7 v1(1642.1,1920.35)
  BOTTOM w10: 1433.55,1110.5 1491.95,1110.5 1552.8,1171.35 1578.95,1171.35 1590.95,1171.35
  BOTTOM w20: 1644.75,1939 1644.75,2051.1 1670.36,2076.71 R120.2@1670.75,2077.1
  other v1: 1688.85,1807.7 1657.55,1824.4 1646.75,1855.2 1641.35,1886.2
PMIC_2V3: C21.2 C23.2 C25.2 C82.2 L3.2 L5.1 R84.1 U4.7 U4.8 U8.21 | length 718.4
  TOP w20: 1890.65,916.6 1890.65,948.4 1955.97,1013.72 R84.1@1980.42,1013.72 R84.1@1981.2,1013.72
  BOTTOM w10: 1716.55,1171.35 1728.55,1171.35 1772.4,1171.35 1819.15,1124.6 1819.15,1110.8 1845.35,1084.6 1890.35,1084.6 1911.05,1063.9 1911.05,945.81 1852.74,887.5 L3.2@1805.23,887.5 ; v1(2216.25,1032.4) v1@2253.05,1032.4 ; L5.1@2242.55,1064.43 L5.1@2242.55,1062.46 2242.55,1042.9 v1@2253.05,1032.4 ; v1(2253.55,1031.9) v1@2253.05,1032.4
  other v1: 1858.75,812 1900.75,815 1870.75,848 1917.75,852 2152.65,984.4 2189.95,983.9
PMIC_CLK: R97.2 U8.3 | length 1772.1
  TOP w7.08: v1(1418.25,822.7) 1462.85,867.3 1462.85,1005 1453.65,1014.2 1453.65,1111.9 v1(1473.05,1131.3)
  TOP w11: R97.2@387.75,690.55 388.14,690.94 397.75,700.55 v1(397.75,769)
  L3-GND/SIG w9: v1(397.75,769) 397.75,803.5 471.58,877.33 784.92,877.33 880.15,782.1 983.15,782.1 1035.85,729.4 1164.65,729.4 1182.75,747.5 1182.75,757.5 1202.75,777.5 1373.05,777.5 v1(1418.25,822.7)
  BOTTOM w9: v1(1473.05,1131.3) 1489.05,1131.3 1527.75,1170 1527.75,1201.9 1540.05,1214.2 1578.22,1214.2 U8.3@1578.95,1213.47
PMIC_EN1: R102.2 R142.1 U8.7 | length 1317.7
  TOP w4: R102.2@1333,675.77 1333,769.15 1419.65,855.8 1419.65,1105.69 1478.25,1164.29 1478.25,1260.8 1505.65,1288.2 v1(1546.05,1288.2) 1551.35,1293.5 1859.05,1293.5 1907.05,1245.5 1954.75,1245.5 1974.12,1226.13 v1(1989.49,1226.13)
  BOTTOM w4: v1(1546.05,1288.2) 1550.06,1292.21 U8.7@1578.95,1292.21 ; R142.1@1985,1309.54 1985,1230.62 v1(1989.49,1226.13)
PMIC_EN2: R148.1 U8.15 | length 512.7
  L3-GND/SIG w5: v1(1919.75,1337.4) 1920.65,1337.4 1942.9,1315.15 1942.9,1138.85 1926,1121.95 v1(1926,1116)
  BOTTOM w4: U8.15@1728.55,1292.21 1832.96,1292.21 1846.95,1306.2 1888.55,1306.2 v1(1919.75,1337.4) ; v1(1926,1116) 1947.65,1116 1977.36,1145.71 R148.1@1977.75,1146.1
PMIC_EN3: R145.1 U8.2 | length 543.1
  TOP w4: v1(1549.85,1193.79) 1583.05,1226.99 1583.05,1264.5 1603.55,1285 1856.15,1285 1897.85,1243.3 v1(1897.85,1221)
  BOTTOM w4: v1(1549.85,1193.79) U8.2@1578.95,1193.79 ; v1(1897.85,1221) 1897.85,1241.6 1916.43,1260.18 R145.1@1936.19,1260.18
PMIC_NRST: R150.2 U8.20 | length 227.8
  BOTTOM w4: U8.20@1728.55,1193.79 1774.95,1193.79 1807.74,1161 1871.55,1161 1886.8,1145.75 R150.2@1936.49,1145.75
PMICOUT_3V3: C55.2 L2.2 R133.1 R141.1 U8.8 | length 511.4
  BOTTOM w10: U8.8@1583.75,1314.65 1590.95,1314.65
  BOTTOM w15: 1464.69,1386.96 1523.05,1328.6 1523.05,1320.1 1528.14,1315.01 R141.1@1528.5,1314.65 ; R141.1@1528.54,1314.65 1578.95,1314.65 U8.8@1583.75,1314.65
  BOTTOM w20: 1464.69,1386.96 1433.69,1386.96 1418.75,1401.9 1418.75,1493.85 1437.1,1512.2 1438.45,1512.2 1456.75,1530.5 1456.75,1562.69 1471.82,1577.76 L2.2@1500.11,1577.76 ; 1468.85,1664.1 R133.1@1468.85,1698.2 1505.95,1698.2
PMICVIO_3V3: R139.2 R142.2 R143.2 R145.2 R147.2 R148.2 R149.1 R150.1 | length 377
  BOTTOM w20: R147.2@1896.65,1183 R147.2@1897.44,1183 1935.94,1183 R150.1@1936.49,1183.55 ; R143.2@1897.15,1284.3 R143.2@1897.94,1284.3 1915.65,1284.3 1918.15,1286.8 1921.56,1286.8 1943.76,1309 1946.41,1309 1946.66,1309 1946.81,1309.15 R142.2@1947.2,1309.54 ; R139.2@1947.2,1350.04 R142.2@1947.2,1309.54 ; R149.1@2018.89,1183.55 2018.54,1183.9 1977.75,1183.9 1977.4,1183.55 R150.1@1936.49,1183.55 ; R150.1@1936.49,1183.55 R150.1@1936.49,1184.33 1936.49,1220.81 1936.49,1223.45 1936.19,1223.75 1943.5,1223.75 1944.75,1225 1949.75,1225 1965.75,1241 1965.75,1277.5 1947.2,1296.05 R142.2@1947.2,1309.54
RX1: U2.M2 | length 194.8
  TOP w7.08: U2.M2@2550.84,1742.76 2590.93,1742.76 ccw(c2590.93,1859.34) 2660.87,1766.07 ; 2660.9,1766.1 cw(c2700.52,1706.69) 2700.49,1778.1 2738.15,1778.1
RX2: U2.K2 | length 194.9
  TOP w7.08: U2.K2@2550.84,1691.58 2610.71,1691.58 ccw(c2610.71,1772.49) 2657.97,1706.82 ; 2657.99,1706.84 cw(c2682.71,1672.7) 2682.4,1714.85 2699.85,1714.98 cw(c2700.05,1687.18) 2719.71,1706.83 ; 2719.71,1706.82 ccw(c2731.34,1724.27) 2731.34,1703.3 2738.01,1703.3
RX3: U2.H2 | length 194.9
  TOP w7.08: U2.H2@2550.84,1640.4 2610.71,1640.4 cw(c2610.71,1559.49) 2657.97,1625.16 ; 2657.99,1625.14 ccw(c2682.71,1659.28) 2682.4,1617.13 2699.85,1617 ccw(c2700.05,1644.8) 2719.71,1625.15 cw(c2731.34,1607.71) 2731.34,1628.68 2738.01,1628.68
RX4: U2.F2 | length 194.7
  TOP w7.08: U2.F2@2550.84,1589.22 2590.93,1589.22 cw(c2590.93,1472.64) 2660.87,1565.91 ; 2660.9,1565.88 ccw(c2700.52,1625.29) 2700.49,1553.88 2738.15,1553.88
SPICLK1: R75.1 R76.1 U14.8 | length 272
  TOP w4: U14.8@1229.28,1344.01 1229.28,1345.83 1229.28,1371.81 1238.29,1380.82 1274.23,1380.82 1307.06,1347.99 1336.47,1347.99 1344.97,1356.49 R75.1@1346.75,1356.49 1337.49,1365.75 1337.49,1376.24 1342.07,1380.82 1386.62,1380.82 1391.5,1375.94 1391.5,1368.24 R76.1@1379.75,1356.49
SS_CTRL: R119.2 R120.1 U5.8 U5.18 | length 1094
  L4-GND/SIG w5: v1(1635.75,1711.5) 1635.75,1722 1604.45,1753.3 1604.45,1969.21 1637.75,2002.51 1637.75,2095.7 1676.95,2134.9 v1(1676.95,2189.2)
  BOTTOM w4: v1(1635.75,1711.5) 1648.75,1698.5 1724.74,1698.5 1740.75,1714.51 1740.75,1767.01 1757.37,1783.63 U5.18@1757.37,1808.08 ; R120.1@1670.75,2114.9 1671.14,2115.29 1676.95,2121.1 v1(1676.95,2189.2) 1711.15,2189.2 1756.46,2143.89 1759.75,2140.6 1759.75,1967.94 U5.8@1757.37,1965.56
SW0: L2.1 R202.2 U8.10 | length 332.1
  BOTTOM w10: 1615.26,1379.5 1634.06,1360.7 U8.10@1634.06,1303.63
  BOTTOM w14.5: 1552.57,1500.03 1583.6,1469 1583.6,1396.5
  BOTTOM w17: 1583.6,1396.5 1600.6,1379.5 1615.26,1379.5
  BOTTOM w20: R202.2@1494.45,1455.3 R202.2@1494.45,1456.09 1494.45,1483.88 1509.62,1499.05 L2.1@1510.6,1500.03
  BOTTOM w25: L2.1@1510.6,1500.03 1552.57,1500.03
SW1: L1.1 R203.2 U8.12 | length 337.9
  BOTTOM w10: U8.12@1673.43,1303.63 1673.44,1361.74 1693.7,1382
  BOTTOM w14.5: 1724.7,1397.9 1724.7,1469.7 1755.43,1500.43
  BOTTOM w17: 1693.7,1382 1708.8,1382 1724.7,1397.9
  BOTTOM w20: L1.1@1796.8,1500.43 1801.92,1500.43 1816.07,1486.28 1816.07,1457.02 1814.64,1455.59 R203.2@1814.25,1455.2
  BOTTOM w25: 1755.43,1500.43 L1.1@1796.8,1500.43
SW2: L4.1 R204.2 U8.25 | length 359.3
  BOTTOM w10: 1624.3,1093.3 1634.06,1103.06 U8.25@1634.06,1182.37
  BOTTOM w14.5: 1548.67,963.67 1582.6,997.6 1582.6,1068
  BOTTOM w17: 1582.6,1068 1599.6,1085 1616,1085 1624.3,1093.3
  BOTTOM w20: R204.2@1493.45,1010.4 R204.2@1493.45,1009.61 1493.45,974.52 1503.32,964.65 L4.1@1504.3,963.67
  BOTTOM w25: L4.1@1504.3,963.67 1548.67,963.67
SW3: L3.1 R205.2 U8.23 | length 383.8
  BOTTOM w10: U8.23@1673.43,1182.37 1673.44,1106.82 1691.26,1089
  BOTTOM w14.5: 1721.4,1073.2 1721.4,997.2 1753.59,965.01
  BOTTOM w17: 1691.26,1089 1705.6,1089 1721.4,1073.2 ; 1753.59,965.01 1755.43,965.01
  BOTTOM w20: L3.1@1796.3,963.67 1821.32,963.67 1836.55,978.9 1836.55,1013.11 1836.55,1013.8 R205.2@1836.65,1013.9
  BOTTOM w25: 1755.43,965.01 1756.77,963.67 L3.1@1796.3,963.67
TX1: U2.B4 | length 817.7
  TOP w7.08: U2.B4@2499.66,1486.86 2499.66,1082.11 ccw(c2557.07,1082.11) 2557.07,1024.7 2569.35,1024.7 ccw(c2569.35,1082.7) 2627.35,1082.7 2627.35,1159.24 cw(c2666.61,1159.24) 2638.85,1187 cw(c2676.01,1149.87) 2676.01,1202.4 2746.75,1202.4
TX2: U2.B6 | length 815.1
  TOP w7.08: U2.B6@2448.48,1486.86 2448.48,1052.03 ccw(c2597.31,1052.03) 2597.31,903.2 2743.75,903.2
VBUS_1_DETECT: C69.2 R151.1 R153.2 U6.1 | length 147.8
  BOTTOM w7: 266.7,1166.45 U6.1@311.39,1166.45
  BOTTOM w20: R153.2@249.3,1080.24 249.3,1123.54 249.69,1123.93 249.7,1166.06 C69.2@250.09,1166.06 266.31,1166.06 266.7,1166.45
